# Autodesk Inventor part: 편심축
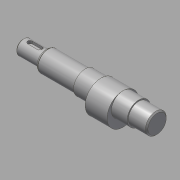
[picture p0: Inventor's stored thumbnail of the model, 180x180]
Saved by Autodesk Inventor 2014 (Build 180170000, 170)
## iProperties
Created: 2017-08
Part Number: 편심축
Material: 강철, 연강
Document SubType Name: Modeling
Designer: mduedu
Density: 1 g/cm^3
Appearance: Steel
Author: mduedu
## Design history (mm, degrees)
sketch "스케치1"
  geometry: L1 (0, 0)-(110, 0); L2 (110, 0)-(110, 8.5); L3 (110, 8.5)-(95, 8.5); L4 (95, 8.5)-(95, 9.5); L5 (95, 9.5)-(51, 9.5); L6 (51, 9.5)-(51, 8.5); L7 (51, 8.5)-(19, 8.5); L8 (19, 8.5)-(19, 6); L9 (19, 6)-(0, 6); L10 (0, 6)-(0, 0)
  constraints: 20 end point, 6 parallel, 2 collinear, 2 perpendicular, 1 horizontal
  dimensions: "d0" = 110 distance of L1.start L1.end; "d1" = 17 diameter of L3 L1; "d2" = 19 diameter of L5 L1; "d3" = 12 diameter of L9 L1; "d4" = 19 distance of L8.end L9.end; "d5" = 15 distance of L2.end L3.end; "d6" = 44 distance of L4.end L5.end
revolve "회전1" sketch "스케치1" stored, may be unused: angle "d7" = 90 deg
node "작업 평면1"
sketch "스케치2"
  geometry: C1 r 9.5 at (0, 0) reference; C2 r 13 at (0, -3.5); 1 further point
  constraints: 1 centre point, 1 tangent, 1 vertical alignment
  dimensions: "d8" = 3.5 distance of point (0, 0) C2.centre
extrude "돌출1" join sketch "스케치2" stored distance "d9" = 18; taper "d10" = 0 deg
chamfer "모따기1" distance "d11" = 1; stored, may be unused: second distance "d12" = 2, angle "d13" = 45 deg
node "작업 평면2"
sketch "스케치3"
  geometry: L1 (3.5, -2)-(-4.5, -2); L2 (-4.5, -2)-(-4.5, 2); L3 (-4.5, 2)-(3.5, 2); L4 (3.5, 2)-(3.5, -2); L5 (9.5, 6)-(9.5, -6) reference; A1 r 2 centre (3.5, 0) between (3.5, -2) and (3.5, 2); A2 r 2 centre (-4.5, 0) between (-4.5, 2) and (-4.5, -2); A3 r 2 centre (3.5, 0) between (3.5, 2) and (3.5, -2); A4 r 2 centre (-4.5, 0) between (-4.5, -2) and (-4.5, 2); 1 further point
  constraints: 8 end point, 8 point on circle, 4 centre point, 2 midpoint, 2 parallel, 1 horizontal, 1 horizontal alignment, 1 perpendicular
  dimensions: "d14" = 12 dimension on A2 A1; "d16" = 4 distance between parallel lines of L3 L1; "d17" = 4 distance edge to line of A1 L5
extrude "돌출2" cut sketch "스케치3" distance "d18" = 2.5; taper "d19" = 0 deg
chamfer "모따기2" distance "d20" = 1; stored, may be unused: second distance "d21" = 2, angle "d22" = 45 deg
chamfer "모따기3" distance "d23" = 1; stored, may be unused: second distance "d24" = 2, angle "d25" = 60 deg
fillet "모깎기1" dims "d26" = 0.5
hole "구멍1" diameter "d29" = 3.242; stored, may be unused: countersink angle "d33" = 90 deg, drill point angle "d35" = 118 deg; dims "d30" = 8, "d31" = 4, "d32" = 2, "d34" = 10, "d36" = 10, "d37" = 10
node "솔리드1"
node "절단 모서리 투영1"
